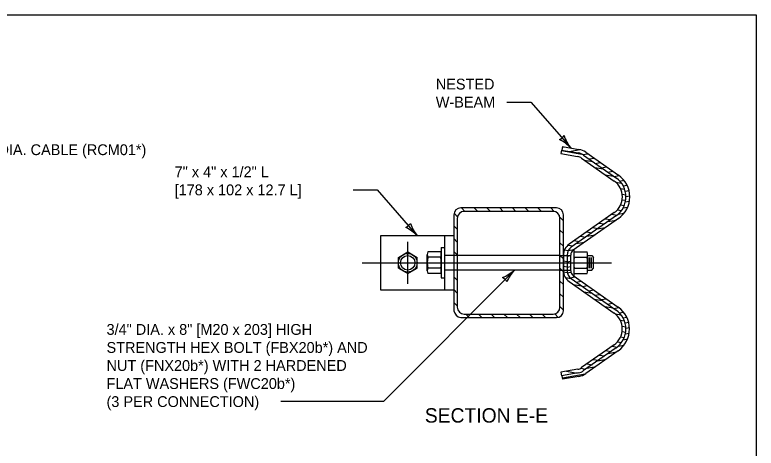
# Model space of a CAD drawing. Extents: x 49991.4 to 50021, y 49987.6 to 50011.4.
# Drawn here: x 50012.637 to 50016.75, y 49996.597 to 49998.999 of the extents above; entities that cross this region are included whole.
import ezdxf

# ---------------------------------------------------------------- set-up
doc = ezdxf.new("R2010")
doc.units = 0
for name, color, linetype in [('Level 1', 7, 'Continuous'), ('Level 2', 7, 'Continuous'), ('Level 3', 7, 'Continuous'), ('Level 4', 7, 'Continuous'), ('Level 5', 7, 'Continuous')]:
    doc.layers.add(name, color=color, linetype=linetype)

msp = doc.modelspace()

# ---------------------------------------------------------------- linework, layer by layer
at = {"layer": 'Level 1'}
for p, q in [((50015.6756, 49998.269), (50015.6723, 49998.2493)), ((50015.675, 49998.2656), (50015.685, 49998.2674)), ((50015.6756, 49998.269), (50015.7665, 49998.2531)), ((50015.6696, 49998.2498), (50015.6662, 49998.2301)), ((50015.6662, 49998.2301), (50015.7596, 49998.2137)), ((50015.6691, 49998.2471), (50015.7829, 49998.2271)), ((50015.6696, 49998.2498), (50015.7631, 49998.2334)), ((50015.7139, 49998.242), (50015.7714, 49998.2522)), ((50015.7875, 49998.2245), (50015.8158, 49998.2295)), ((50015.7929, 49998.2212), (50015.9742, 49998.0939)), ((50015.8044, 49998.2375), (50015.9857, 49998.1103)), ((50015.7814, 49998.2048), (50015.9627, 49998.0775)), ((50015.7965, 49998.1942), (50015.843, 49998.186)), ((50015.8227, 49998.2003), (50015.8505, 49998.2052)), ((50015.8574, 49998.1759), (50015.8851, 49998.1808)), ((50015.8544, 49998.1535), (50015.9009, 49998.1453)), ((50015.892, 49998.1516), (50015.9198, 49998.1565)), ((50015.9124, 49998.1128), (50015.9589, 49998.1046)), ((50015.9268, 49998.1273), (50015.9545, 49998.1321)), ((50015.9614, 49998.1029), (50015.9892, 49998.1078)), ((50015.9695, 49998.0723), (50016.0022, 49998.0665)), ((50015.9926, 49998.0779), (50016.0164, 49998.0821)), ((50015.9971, 49998.037), (50016.0203, 49998.0329)), ((50016.0122, 49998.0509), (50016.0341, 49998.0548)), ((50016.0234, 49998.0224), (50016.0447, 49998.0262)), ((50016.0067, 49997.9744), (50016.0261, 49997.9709)), ((50016.0069, 49998.0048), (50016.0271, 49998.0012)), ((50016.0275, 49997.9927), (50016.0491, 49997.9965)), ((50015.998, 49997.9454), (50016.018, 49997.9419)), ((50016.0119, 49997.929), (50016.0377, 49997.9336)), ((50016.0241, 49997.9616), (50016.0471, 49997.9657)), ((50015.093, 49997.8799), (50015.0738, 49997.8991)), ((50015.6423, 49997.9285), (50015.1111, 49997.9285)), ((50015.1343, 49997.9093), (50015.1151, 49997.9285)), ((50015.6231, 49997.9093), (50015.1303, 49997.9093)), ((50015.205, 49997.9093), (50015.1858, 49997.9285)), ((50015.2757, 49997.9093), (50015.2565, 49997.9285)), ((50015.3464, 49997.9093), (50015.3272, 49997.9285)), ((50015.4171, 49997.9093), (50015.3979, 49997.9285)), ((50015.4878, 49997.9093), (50015.4686, 49997.9285)), ((50015.5585, 49997.9093), (50015.5393, 49997.9285)), ((50015.6298, 49997.9087), (50015.6101, 49997.9285)), ((50015.9627, 49997.9029), (50015.712, 49997.7274)), ((50015.9488, 49997.8932), (50015.9766, 49997.8883)), ((50015.9799, 49997.9182), (50016.0024, 49997.9142)), ((50015.983, 49997.8935), (50016.0174, 49997.8995)), ((50015.0727, 49997.8901), (50015.0727, 49997.3589)), ((50015.0919, 49997.8709), (50015.0919, 49997.3781)), ((50015.6807, 49997.8578), (50015.661, 49997.8776)), ((50015.6615, 49997.3781), (50015.6615, 49997.8709)), ((50015.6807, 49997.3589), (50015.6807, 49997.8901)), ((50015.9742, 49997.8866), (50015.7234, 49997.711)), ((50015.9857, 49997.8702), (50015.7349, 49997.6946)), ((50015.914, 49997.8688), (50015.9419, 49997.8639)), ((50015.9262, 49997.853), (50015.9729, 49997.8612)), ((50015.9857, 49997.8702), (50015.9857, 49997.8702)), ((50015.0919, 49997.8102), (50015.0727, 49997.8294)), ((50015.8445, 49997.8202), (50015.8724, 49997.8153)), ((50015.8681, 49997.8123), (50015.9147, 49997.8205)), ((50015.8793, 49997.8445), (50015.9071, 49997.8396)), ((50015.0727, 49997.7745), (50014.6647, 49997.7745)), ((50014.6647, 49997.7745), (50014.6647, 49997.4745)), ((50015.0219, 49997.4745), (50015.0219, 49997.7745)), ((50015.6807, 49997.7871), (50015.6615, 49997.8063)), ((50015.775, 49997.7715), (50015.8028, 49997.7666)), ((50015.8097, 49997.7958), (50015.8376, 49997.7909)), ((50015.8099, 49997.7716), (50015.8565, 49997.7798)), ((50015.0919, 49997.7395), (50015.0727, 49997.7587)), ((50015.6807, 49997.7164), (50015.6615, 49997.7356)), ((50015.7402, 49997.7472), (50015.7681, 49997.7423)), ((50015.7517, 49997.7308), (50015.7984, 49997.7391)), ((50015.002, 49997.7085), (50015.0219, 49997.7085)), ((50015.002, 49997.7085), (50015.002, 49997.5406)), ((50015.0919, 49997.6688), (50015.0727, 49997.688)), ((50015.6864, 49997.6957), (50015.7068, 49997.6921)), ((50015.706, 49997.7228), (50015.7333, 49997.7179)), ((50015.707, 49997.6925), (50015.7402, 49997.6983)), ((50015.7375, 49997.6964), (50015.7375, 49997.5516)), ((50014.7648, 49997.6545), (50014.8167, 49997.6845)), ((50014.7648, 49997.5945), (50014.7648, 49997.6545)), ((50014.8167, 49997.6845), (50014.8687, 49997.6545)), ((50014.8687, 49997.5945), (50014.8687, 49997.6545)), ((50014.9249, 49997.5796), (50014.9249, 49997.6694)), ((50014.9996, 49997.6548), (50014.9273, 49997.6548)), ((50014.9995, 49997.6845), (50014.9274, 49997.6845)), ((50015.6615, 49997.6645), (50015.0919, 49997.6645)), ((50015.6807, 49997.6457), (50015.6615, 49997.6649)), ((50015.6807, 49997.6674), (50015.6807, 49997.624)), ((50015.6807, 49997.6663), (50015.7007, 49997.6628)), ((50015.7007, 49997.6674), (50015.7007, 49997.624)), ((50015.7007, 49997.6609), (50015.7207, 49997.6644)), ((50015.7207, 49997.6674), (50015.7207, 49997.624)), ((50015.7399, 49997.6548), (50015.8122, 49997.6548)), ((50015.74, 49997.6845), (50015.8121, 49997.6845)), ((50015.8146, 49997.5796), (50015.8146, 49997.6694)), ((50015.8146, 49997.6645), (50015.8381, 49997.6645)), ((50015.817, 49997.5945), (50015.817, 49997.6545)), ((50015.827, 49997.5945), (50015.827, 49997.6545)), ((50015.837, 49997.5945), (50015.837, 49997.6545)), ((50015.8381, 49997.6645), (50015.8481, 49997.6545)), ((50015.8481, 49997.5945), (50015.8481, 49997.6545)), ((50015.6807, 49997.6358), (50015.7007, 49997.6323)), ((50015.6807, 49997.624), (50015.6807, 49997.5806)), ((50015.6807, 49997.6054), (50015.7007, 49997.6018)), ((50015.7007, 49997.6305), (50015.7207, 49997.634)), ((50015.7007, 49997.624), (50015.7007, 49997.5806)), ((50015.7007, 49997.6), (50015.7207, 49997.6035)), ((50015.7207, 49997.624), (50015.7207, 49997.5806)), ((50014.7648, 49997.5945), (50014.8167, 49997.5645)), ((50014.8167, 49997.5645), (50014.8687, 49997.5945)), ((50014.9996, 49997.5943), (50014.9273, 49997.5943)), ((50014.9995, 49997.5645), (50014.9274, 49997.5645)), ((50015.6615, 49997.5845), (50015.0919, 49997.5845)), ((50015.6807, 49997.575), (50015.6615, 49997.5942)), ((50015.681, 49997.5749), (50015.7016, 49997.5712)), ((50015.7019, 49997.5697), (50015.7216, 49997.5732)), ((50015.7399, 49997.5943), (50015.8122, 49997.5943)), ((50015.74, 49997.5645), (50015.8121, 49997.5645)), ((50015.8146, 49997.5845), (50015.8381, 49997.5845)), ((50015.8381, 49997.5845), (50015.8481, 49997.5945)), ((50015.002, 49997.5406), (50015.0219, 49997.5406)), ((50015.0919, 49997.5274), (50015.0727, 49997.5466)), ((50015.6807, 49997.5043), (50015.6615, 49997.5235)), ((50015.6914, 49997.5425), (50015.7237, 49997.5369)), ((50015.7173, 49997.542), (50015.7444, 49997.5468)), ((50015.7234, 49997.537), (50015.9729, 49997.3624)), ((50015.7349, 49997.5534), (50015.9843, 49997.3788)), ((50015.7513, 49997.5175), (50015.7791, 49997.5224)), ((50015.712, 49997.5206), (50015.9614, 49997.346)), ((50015.7352, 49997.5044), (50015.7818, 49997.4961)), ((50015.786, 49997.4932), (50015.8139, 49997.4981)), ((50014.6647, 49997.4745), (50015.0727, 49997.4745)), ((50015.0919, 49997.4567), (50015.0727, 49997.4759)), ((50015.6807, 49997.4335), (50015.6615, 49997.4527)), ((50015.7934, 49997.4636), (50015.84, 49997.4554)), ((50015.8208, 49997.4688), (50015.8487, 49997.4738)), ((50015.8556, 49997.4445), (50015.8834, 49997.4494)), ((50015.0919, 49997.386), (50015.0727, 49997.4052)), ((50015.8515, 49997.4229), (50015.8981, 49997.4147)), ((50015.8903, 49997.4202), (50015.9182, 49997.4251)), ((50015.9251, 49997.3958), (50015.9529, 49997.4008)), ((50015.6807, 49997.3628), (50015.6615, 49997.382)), ((50015.9097, 49997.3822), (50015.9563, 49997.374)), ((50015.9598, 49997.3715), (50015.9876, 49997.3764)), ((50015.1111, 49997.3205), (50015.6423, 49997.3205)), ((50015.1303, 49997.3397), (50015.6231, 49997.3397)), ((50015.1574, 49997.3205), (50015.1382, 49997.3397)), ((50015.2281, 49997.3205), (50015.2089, 49997.3397)), ((50015.2988, 49997.3205), (50015.2796, 49997.3397)), ((50015.3695, 49997.3205), (50015.3503, 49997.3397)), ((50015.4402, 49997.3205), (50015.421, 49997.3397)), ((50015.511, 49997.3205), (50015.4918, 49997.3397)), ((50015.5817, 49997.3205), (50015.5625, 49997.3397)), ((50015.6513, 49997.3216), (50015.6321, 49997.3408)), ((50015.9673, 49997.3416), (50016.0008, 49997.3357)), ((50015.9914, 49997.3466), (50016.0145, 49997.3507)), ((50016.0113, 49997.3197), (50016.032, 49997.3233)), ((50015.9959, 49997.3061), (50016.0195, 49997.3019)), ((50016.0229, 49997.2912), (50016.0426, 49997.2947)), ((50016.0061, 49997.2738), (50016.0267, 49997.2702)), ((50016.0063, 49997.2433), (50016.026, 49997.2398)), ((50016.0244, 49997.2306), (50016.0454, 49997.2343)), ((50016.0273, 49997.2616), (50016.0471, 49997.2651)), ((50015.9981, 49997.2143), (50016.0183, 49997.2107)), ((50016.0124, 49997.198), (50016.0365, 49997.2022)), ((50015.9615, 49997.1698), (50015.7814, 49997.0432)), ((50015.973, 49997.1534), (50015.7929, 49997.0268)), ((50015.9502, 49997.1618), (50015.9779, 49997.1569)), ((50015.9807, 49997.1869), (50016.0031, 49997.183)), ((50015.9847, 49997.1627), (50016.0171, 49997.1684)), ((50015.9845, 49997.137), (50015.8044, 49997.0105)), ((50015.8809, 49997.1131), (50015.9087, 49997.1082)), ((50015.9156, 49997.1375), (50015.9434, 49997.1326)), ((50015.9288, 49997.1223), (50015.9753, 49997.1305)), ((50015.8463, 49997.0888), (50015.8741, 49997.0839)), ((50015.871, 49997.0817), (50015.9174, 49997.0899)), ((50015.7597, 49997.0342), (50015.6662, 49997.0178)), ((50015.7765, 49997.0401), (50015.8047, 49997.0352)), ((50015.8116, 49997.0644), (50015.8394, 49997.0595)), ((50015.8131, 49997.041), (50015.8595, 49997.0492)), ((50015.6662, 49997.0178), (50015.6696, 49996.9981)), ((50015.7631, 49997.0145), (50015.6696, 49996.9981)), ((50015.6726, 49996.9987), (50015.6761, 49996.979)), ((50015.6748, 49996.9862), (50015.8015, 49997.0085)), ((50015.7666, 49996.9948), (50015.6761, 49996.979)), ((50015.6982, 49997.0235), (50015.756, 49997.0133))]:
    msp.add_line(p, q, dxfattribs=at)
msp.add_lwpolyline([(49999.3835, 49998.9992), (50016.7501, 49998.9992), (50016.7501, 49987.7988), (49999.3835, 49987.7988)], close=True, dxfattribs=at)
for radius in [0.052, 0.04]:
    msp.add_circle((50014.8167, 49997.6245), radius, dxfattribs=at)
for centre, radius, start, end in [((50015.7507, 49998.1612), 0.0733, 54.9095, 80.2724), ((50015.7507, 49998.1612), 0.0933, 54.9095, 80.2724), ((50015.7507, 49998.1612), 0.0533, 54.9095, 80.2724), ((50015.904, 49997.9902), 0.1452, 304.2121, 55.7785), ((50015.9009, 49997.9902), 0.107, 305.3281, 54.6849), ((50015.9003, 49997.9902), 0.1273, 305.4812, 54.5188), ((50015.1111, 49997.8901), 0.0384, 90, 180), ((50015.1303, 49997.8709), 0.0384, 90, 180), ((50015.6231, 49997.8709), 0.0384, 0, 90), ((50015.6423, 49997.8901), 0.0384, 0, 90), ((50015.754, 49997.6674), 0.0732, 125.0223, 180), ((50015.754, 49997.6674), 0.0532, 125.0223, 180), ((50015.754, 49997.6674), 0.0332, 125.0223, 180), ((50015.754, 49997.5806), 0.0732, 180, 234.9777), ((50015.754, 49997.5806), 0.0532, 180, 234.9777), ((50015.754, 49997.5806), 0.0332, 180, 234.9777), ((50015.1175, 49997.3652), 0.0452, 188.0694, 261.9306), ((50015.1305, 49997.3783), 0.0386, 180.2966, 269.7034), ((50015.6231, 49997.3781), 0.0384, 270, 0), ((50015.6423, 49997.3589), 0.0384, 270, 0), ((50015.8997, 49997.2578), 0.1276, 305.0648, 55.0156), ((50015.8997, 49997.2578), 0.1476, 305.0648, 55.0156), ((50015.8997, 49997.2578), 0.1076, 305.0648, 55.0156), ((50015.7507, 49997.0868), 0.0533, 279.7276, 305.0905), ((50015.7507, 49997.0868), 0.0733, 279.7276, 305.0905), ((50015.7507, 49997.0868), 0.0933, 279.7276, 305.0905)]:
    msp.add_arc(centre, radius, start, end, dxfattribs=at)
for centre, major_axis, start_param, end_param in [((50014.9436, 49997.6695), (0, 0.03), 1.047198, 2.084746), ((50014.9998, 49997.6245), (0, 0.12), 1.315951, 1.825641), ((50014.9833, 49997.6695), (0, 0.03), 4.198439, 5.235988), ((50014.9272, 49997.6245), (0, 0.12), 4.457545, 4.967235), ((50015.7562, 49997.6695), (0, 0.03), 1.047198, 2.084746), ((50015.8123, 49997.6245), (0, 0.12), 1.31595, 1.825641), ((50015.7959, 49997.6695), (0, 0.03), 4.198439, 5.235988), ((50015.7397, 49997.6245), (0, 0.12), 4.457545, 4.967234), ((50014.9436, 49997.5795), (0, 0.03), 1.056847, 2.094396), ((50014.9833, 49997.5795), (0, 0.03), 4.188789, 5.226338), ((50015.7562, 49997.5795), (0, 0.03), 1.056847, 2.094396), ((50015.7959, 49997.5795), (0, 0.03), 4.188789, 5.226338)]:
    msp.add_ellipse(centre, major_axis=major_axis, ratio=0.623816, start_param=start_param, end_param=end_param, dxfattribs=at)
at = {"layer": 'Level 3'}
for p, q in [((50015.3662, 49998.5153), (50015.5001, 49998.5153)), ((50015.5001, 49998.5153), (50015.7211, 49998.2611)), ((50014.5138, 49998.0288), (50014.6478, 49998.0288)), ((50014.6478, 49998.0288), (50014.8687, 49997.7745)), ((50015.4088, 49997.5845), (50014.6816, 49996.855)), ((50014.6816, 49996.855), (50014.1127, 49996.855))]:
    msp.add_line(p, q, dxfattribs=at)
for centre, radius, start, end in [((50015.637, 49998.3579), 0.0548, 293.1304, 328.8527), ((50015.5594, 49998.1085), 0.2223, 43.352, 63.5355), ((50015.9043, 49998.4051), 0.233, 198.9144, 218.1642), ((50014.7846, 49997.8713), 0.0548, 293.1304, 328.8527), ((50014.7071, 49997.6219), 0.2223, 43.352, 63.5355), ((50015.0519, 49997.9185), 0.233, 198.9144, 218.1642), ((50015.252, 49997.7569), 0.233, 293.0163, 312.2661), ((50015.5725, 49997.4342), 0.2223, 137.4539, 157.6374), ((50015.3182, 49997.4937), 0.0548, 27.2322, 62.9546)]:
    msp.add_arc(centre, radius, start, end, dxfattribs=at)
at = {"layer": 'Level 4'}
for p, q in [((50015.0919, 49997.6645), (50015.0219, 49997.6645)), ((50015.6615, 49997.6645), (50015.7207, 49997.6645)), ((50015.0919, 49997.5845), (50015.0219, 49997.5845)), ((50015.6615, 49997.5845), (50015.7207, 49997.5845))]:
    msp.add_line(p, q, dxfattribs=at)
at = {"layer": 'Level 5'}
for p, q in [((50014.8167, 49997.5085), (50014.8167, 49997.7405)), ((50014.5647, 49997.6245), (50015.9481, 49997.6245))]:
    msp.add_line(p, q, dxfattribs=at)

# ---------------------------------------------------------------- texts
at = {"layer": 'Level 2'}
for s, height, p in [('NESTED', 0.06, (50014.9724, 49998.5853)), ('W-BEAM', 0.06, (50014.9724, 49998.4853)), ('3/4" [19.1] DIA. CABLE (RCM01*)', 0.06, (50012.1605, 49998.2214)), ('SECTION E-E', 0.08, (50014.9116, 49996.7384))]:
    msp.add_text(s, height=height, dxfattribs=at).set_placement(p)
for s, p in [('7" x 4" x 1/2" L', (50013.5234, 49998.0988)), ('[178 x 102 x 12.7 L]', (50013.5234, 49997.9988)), ('3/4" DIA. x 8" [M20 x 203] HIGH ', (50013.1454, 49997.225)), ('STRENGTH HEX BOLT (FBX20b*) AND ', (50013.1454, 49997.125)), ('NUT (FNX20b*) WITH 2 HARDENED', (50013.1454, 49997.025)), ('FLAT WASHERS (FWC20b*)', (50013.1454, 49996.925)), ('(3 PER CONNECTION)', (50013.1454, 49996.825))]:
    msp.add_text(s, height=0.06, rotation=360, dxfattribs=at).set_placement(p)

doc.saveas('drawing.dxf')
